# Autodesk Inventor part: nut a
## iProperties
Author: Rich
Shininess: 20.0
PropertySet Name: _Private Model Information
Created: 2001-04
Part Number: nut a
Document SubType Name: Modeling
Designer: Rich
Control State: 0
Master: False
Checked Out: False
PropertySet Name: Design Tracking Control
Density: 0.0
Volumn: 0.0
Area: 0.0
PropertySet Name: Model Information
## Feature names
1. Base1
2. Extrusion1
3. Hole1
4. Chamfer1
